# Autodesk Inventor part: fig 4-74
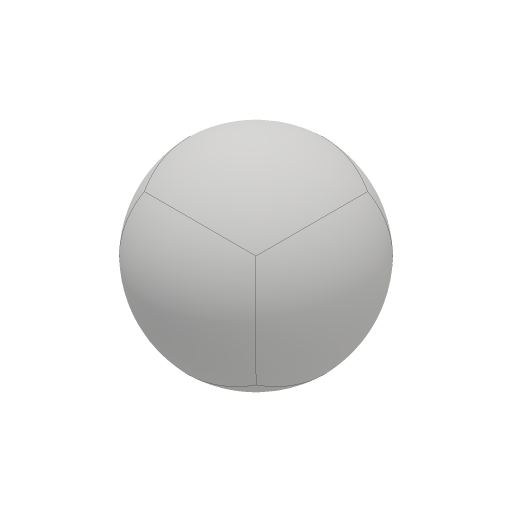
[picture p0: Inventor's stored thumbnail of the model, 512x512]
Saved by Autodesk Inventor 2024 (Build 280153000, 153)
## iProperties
Created: 2015-07
Part Number: fig 4-74
Material: Generic
Document SubType Name: Modeling
Designer: Sandeep
Density: 1 g/cm^3
Appearance: Default
Author: Sandeep
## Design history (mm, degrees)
feature "Form1"
body "Solid1"
